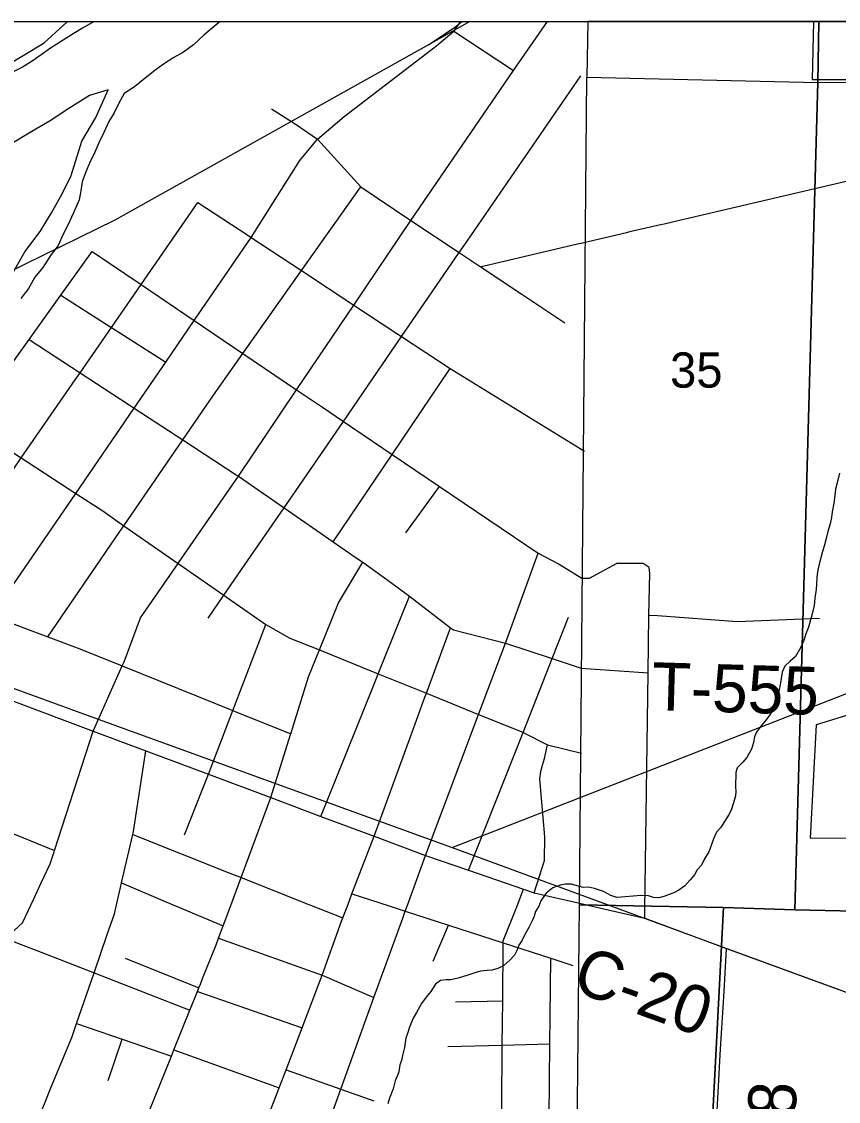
# Model space of a CAD drawing. Extents: x 0 to 34, y 0 to 22.
# Drawn here: x 24.174 to 25.144, y 19.618 to 20.9 of the extents above; entities that cross this region are included whole.
import ezdxf

# ---------------------------------------------------------------- set-up
doc = ezdxf.new("R2010")
doc.units = 0
for name, color, linetype in [('GM_X_City_Street', 7, 'Continuous'), ('GM_X_County_Road', 7, 'Continuous'), ('GM_X_County_Road_Text', 7, 'Continuous'), ('GM_X_Major_River', 7, 'Continuous'), ('GM_X_Minor_River', 7, 'Continuous'), ('GM_X_Rail_Line', 7, 'Continuous'), ('GM_X_Section', 7, 'Continuous'), ('GM_X_Section_Text', 7, 'Continuous'), ('GM_X_Township_Road', 7, 'Continuous'), ('GM_X_Township_Road_Text', 7, 'Continuous'), ('SH_Data', 7, 'Continuous')]:
    doc.layers.add(name, color=color, linetype=linetype)

msp = doc.modelspace()

# ---------------------------------------------------------------- linework, layer by layer
at = {"layer": 'GM_X_City_Street'}
for p, q in [((24.6877, 20.8886), (24.7583, 20.8418)), ((24.2211, 20.5754), (24.2792, 20.5381)), ((24.6307, 20.2929), (24.6705, 20.3482)), ((24.7491, 20.1622), (24.7876, 20.2689)), ((24.3677, 19.9347), (24.3964, 20.0064)), ((24.1512, 19.9411), (24.2136, 19.9158)), ((24.3064, 19.9349), (24.4215, 19.8892)), ((24.6631, 19.7846), (24.6812, 19.8273)), ((24.4083, 19.8119), (24.5315, 19.7681)), ((24.2976, 19.788), (24.3849, 19.753)), ((24.5315, 19.7681), (24.5928, 19.7413)), ((24.3832, 19.7487), (24.5076, 19.7055)), ((24.6896, 19.7363), (24.7457, 19.7375)), ((24.2773, 19.6427), (24.2938, 19.6918)), ((24.3553, 19.6792), (24.4804, 19.634))]:
    msp.add_line(p, q, dxfattribs=at)
for points in [[(23.8108, 20.6025), (23.8574, 20.6229), (23.8812, 20.6383), (23.9238, 20.6791), (23.9884, 20.7438), (24.0412, 20.7796), (24.1024, 20.8136), (24.1535, 20.846), (24.2011, 20.8749), (24.2281, 20.8995), (24.2286, 20.9)], [(24.5258, 20.7605), (24.5574, 20.7874), (24.6301, 20.8431), (24.6673, 20.8716), (24.6877, 20.8886), (24.6961, 20.9)], [(25.6303, 20.9), (25.1147, 20.9), (25.113, 20.8313), (25.279, 20.8313)], [(24.396, 20.1918), (24.4146, 20.2189), (24.4391, 20.2546), (24.486, 20.3228), (24.5565, 20.4254), (24.6256, 20.5261), (24.694, 20.6257), (24.7035, 20.6395), (24.8383, 20.8358)], [(24.4711, 20.7965), (24.4991, 20.7787), (24.5258, 20.7605)], [(24.2057, 20.1696), (24.2904, 20.2933), (24.296, 20.3014), (24.3658, 20.4034), (24.4023, 20.4566), (24.4372, 20.5061), (24.5068, 20.6044), (24.5772, 20.704)], [(24.1146, 20.2964), (24.1707, 20.3774), (24.174, 20.3822), (24.238, 20.4747), (24.2439, 20.4832), (24.2811, 20.5369), (24.3163, 20.5878), (24.3838, 20.6853)], [(24.3838, 20.6853), (24.4429, 20.6464), (24.4471, 20.6436), (24.5068, 20.6044), (24.5688, 20.5635), (24.6201, 20.5297)], [(24.0071, 20.2716), (24.0402, 20.3202), (24.0737, 20.3693), (24.1119, 20.4227), (24.1834, 20.5227), (24.2211, 20.5754), (24.2581, 20.6272)], [(24.2581, 20.6272), (24.3163, 20.5878), (24.3795, 20.5451), (24.4372, 20.5061), (24.501, 20.4629), (24.5317, 20.4422), (24.5565, 20.4254), (24.6145, 20.3861), (24.6705, 20.3482), (24.7876, 20.2689), (24.8126, 20.2557), (24.8395, 20.2394), (24.8488, 20.2394), (24.8808, 20.2567)], [(24.72, 20.6084), (24.7682, 20.5764), (24.8194, 20.5424)], [(24.2792, 20.5381), (24.2811, 20.5369), (24.3456, 20.4956)], [(24.6201, 20.5297), (24.6256, 20.5261), (24.6834, 20.488), (24.8428, 20.3902)], [(24.1834, 20.5227), (24.2439, 20.4832), (24.3021, 20.4451), (24.3082, 20.4411), (24.3658, 20.4034), (24.4293, 20.362), (24.4318, 20.3603)], [(24.5444, 20.2824), (24.6145, 20.3861), (24.6834, 20.488)], [(24.1135, 20.4217), (24.174, 20.3822), (24.2388, 20.3399), (24.2707, 20.319), (24.296, 20.3014), (24.3603, 20.2567), (24.4146, 20.2189), (24.4202, 20.215), (24.4645, 20.1842), (24.493, 20.1681), (24.528, 20.154), (24.5329, 20.152), (24.5978, 20.1257), (24.6551, 20.1026), (24.7171, 20.0775), (24.7676, 20.0571), (24.7698, 20.056), (24.799, 20.0413), (24.8394, 20.0315)], [(23.9157, 20.2781), (23.992, 20.2495), (24.1398, 20.1943), (24.2057, 20.1696), (24.2435, 20.1555), (24.2939, 20.1351), (24.4254, 20.082), (24.428, 20.0809), (24.494, 20.0543)], [(24.5298, 19.9564), (24.5921, 20.1114), (24.5978, 20.1257), (24.6349, 20.218)], [(24.7052, 19.8924), (24.7698, 20.056), (24.8017, 20.1367), (24.8045, 20.1438), (24.8239, 20.1931)], [(24.3964, 20.0064), (24.4254, 20.082), (24.4645, 20.1842)], [(24.5929, 19.9328), (24.6366, 20.052), (24.6534, 20.0979), (24.6551, 20.1026), (24.6836, 20.1804)], [(24.7491, 20.1622), (24.8045, 20.1438), (24.8103, 20.1419), (24.839, 20.1323)], [(25.3319, 20.1309), (25.1177, 20.0653), (25.1107, 19.9304), (25.1891, 19.9311)], [(24.7832, 19.8656), (24.7953, 19.9041), (24.7958, 19.9323), (24.7898, 20.0012), (24.7909, 20.0098), (24.7931, 20.0174), (24.7953, 20.025), (24.799, 20.0413)], [(23.9629, 19.1735), (24.0008, 19.2519), (24.0497, 19.3384), (24.0703, 19.3742), (24.112, 19.4297), (24.1428, 19.4837), (24.1587, 19.5115), (24.2023, 19.6172), (24.2092, 19.6341), (24.2339, 19.694), (24.2396, 19.7104), (24.2604, 19.7707), (24.2761, 19.816), (24.2847, 19.8408), (24.2883, 19.8565), (24.2919, 19.8721), (24.2931, 19.8774), (24.3064, 19.9349), (24.3072, 19.9386), (24.3221, 20.0342)], [(24.4571, 19.5738), (24.4804, 19.634), (24.4886, 19.6556), (24.5076, 19.7055), (24.5315, 19.7681), (24.5544, 19.8322), (24.5557, 19.8359), (24.5616, 19.8511), (24.5667, 19.8645), (24.5929, 19.9328)], [(24.4215, 19.8892), (24.4351, 19.8838), (24.5153, 19.852), (24.5557, 19.8359)], [(24.2931, 19.8774), (24.345, 19.8554), (24.4137, 19.8263)], [(24.5667, 19.8645), (24.611, 19.8501), (24.6229, 19.8462), (24.63, 19.8439), (24.6812, 19.8273), (24.7462, 19.8063), (24.8027, 19.7879), (24.8291, 19.7794)], [(24.7446, 19.4144), (24.7446, 19.4593), (24.7446, 19.5266), (24.7446, 19.557), (24.7445, 19.5967), (24.7447, 19.6129), (24.7452, 19.6848), (24.7455, 19.7113), (24.7457, 19.7375), (24.7462, 19.8063), (24.7462, 19.8086), (24.7615, 19.8472), (24.7705, 19.8699)], [(24.7446, 19.4593), (24.7713, 19.4585), (24.7875, 19.4618), (24.7908, 19.4629), (24.7967, 19.4657), (24.7986, 19.4681), (24.7994, 19.4715), (24.8, 19.5289), (24.8003, 19.5559), (24.8016, 19.6863), (24.802, 19.7187), (24.8027, 19.7879)], [(24.2396, 19.7104), (24.2938, 19.6918), (24.3523, 19.6717)], [(24.6807, 19.6831), (24.7452, 19.6848), (24.8016, 19.6863)], [(24.4886, 19.6556), (24.5535, 19.6327), (24.5928, 19.6189)]]:
    msp.add_lwpolyline(points, dxfattribs=at)
at = {"layer": 'GM_X_County_Road'}
for p, q in [((24.8389, 19.8528), (24.8672, 19.8463)), ((24.1554, 19.8116), (24.203, 19.7931))]:
    msp.add_line(p, q, dxfattribs=at)
for points in [[(24.6366, 20.664), (24.7583, 20.8418), (24.7987, 20.9)], [(24.138, 20.19), (24.1398, 20.1943), (24.1411, 20.1974), (24.1645, 20.2315), (24.2388, 20.3399), (24.3082, 20.4411), (24.3456, 20.4956), (24.3795, 20.5451), (24.4471, 20.6436), (24.5049, 20.7351), (24.5258, 20.7605)], [(24.5258, 20.7605), (24.5772, 20.704), (24.6366, 20.664)], [(24.9673, 20.6671), (25.2835, 20.741), (25.2924, 20.7431)], [(24.9372, 20.6601), (24.9624, 20.666), (24.9673, 20.6671)], [(24.3609, 20.2575), (24.4318, 20.3603), (24.501, 20.4629), (24.5688, 20.5635), (24.6366, 20.664)], [(24.6366, 20.664), (24.694, 20.6257), (24.72, 20.6084), (24.721, 20.6091)], [(24.8982, 20.651), (24.9332, 20.6591), (24.9372, 20.6601)], [(24.8389, 20.6371), (24.8943, 20.65), (24.8982, 20.651)], [(24.721, 20.6091), (24.7221, 20.6098), (24.8359, 20.6364), (24.8389, 20.6371)], [(24.4318, 20.3603), (24.486, 20.3228), (24.5444, 20.2824), (24.5718, 20.2635)], [(24.2962, 20.1401), (24.2974, 20.1429), (24.3156, 20.192), (24.3603, 20.2567), (24.3609, 20.2575)], [(24.4704, 19.9787), (24.4937, 20.0535), (24.494, 20.0543), (24.515, 20.122), (24.528, 20.154), (24.5507, 20.2098), (24.5796, 20.2581)], [(24.5718, 20.2635), (24.5796, 20.2581), (24.6123, 20.2344), (24.6349, 20.218), (24.6836, 20.1804), (24.6872, 20.1777), (24.7491, 20.1622)], [(24.6539, 19.91), (24.7171, 20.0775), (24.7491, 20.1622)], [(24.2131, 19.9143), (24.2136, 19.9158), (24.2595, 20.0576), (24.2939, 20.1351), (24.2962, 20.1401)], [(24.1067, 20.1148), (24.2595, 20.0576), (24.3221, 20.0342), (24.3964, 20.0064), (24.4704, 19.9787), (24.5298, 19.9564), (24.5929, 19.9328), (24.6539, 19.91), (24.7052, 19.8924), (24.7705, 19.8699), (24.7832, 19.8656), (24.8389, 19.8528)], [(24.4215, 19.8474), (24.4239, 19.8538), (24.4351, 19.8838), (24.4704, 19.9787)], [(24.1978, 19.8774), (24.2084, 19.9), (24.2131, 19.9143)], [(24.627, 19.8356), (24.63, 19.8439), (24.6321, 19.8497), (24.6539, 19.91)], [(24.1554, 19.8116), (24.1754, 19.8299), (24.1889, 19.8585), (24.1978, 19.8774)], [(24.3893, 19.7639), (24.4054, 19.8041), (24.4083, 19.8119), (24.4137, 19.8263), (24.4215, 19.8474)], [(24.8672, 19.8463), (24.9143, 19.8355), (25.0113, 19.7995)], [(24.5165, 19.5304), (24.5535, 19.6327), (24.5928, 19.7413), (24.627, 19.8356)], [(25.0013, 19.6291), (25.0041, 19.6803), (25.0087, 19.7486), (25.0113, 19.7995)], [(25.0113, 19.7995), (25.3711, 19.6682), (25.4041, 19.6559)], [(24.203, 19.7931), (24.2604, 19.7707), (24.3743, 19.7264)], [(24.3256, 19.6051), (24.3523, 19.6717), (24.3553, 19.6792), (24.3743, 19.7264), (24.3832, 19.7487), (24.3849, 19.753), (24.3867, 19.7574), (24.3893, 19.7639)], [(24.9991, 19.5889), (24.9994, 19.593), (25.0013, 19.6291)]]:
    msp.add_lwpolyline(points, dxfattribs=at)
at = {"layer": 'GM_X_Major_River'}
for points in [[(24.2606, 20.9), (24.2578, 20.8984), (24.2467, 20.8921), (24.2356, 20.8854), (24.2238, 20.8779), (24.2089, 20.8686), (24.1978, 20.8607), (24.1871, 20.8529), (24.1756, 20.8458), (24.163, 20.8394)], [(24.4101, 20.9), (24.3911, 20.8841), (24.3785, 20.8724), (24.3666, 20.8638), (24.3552, 20.8575), (24.343, 20.8493), (24.3326, 20.8418), (24.3211, 20.8328), (24.3085, 20.8227), (24.2963, 20.8145), (24.2897, 20.8032), (24.2843, 20.7918), (24.2781, 20.7813), (24.2719, 20.7684), (24.266, 20.756), (24.2613, 20.745), (24.2551, 20.7318), (24.2508, 20.7216), (24.2465, 20.7099), (24.2449, 20.6989), (24.2429, 20.6883), (24.2362, 20.6728), (24.2293, 20.6584), (24.2238, 20.6478), (24.218, 20.6342), (24.2095, 20.6233), (24.1995, 20.6079), (24.1902, 20.5966), (24.1825, 20.583), (24.1736, 20.5713)], [(24.2774, 20.8189), (24.2549, 20.8123), (24.2305, 20.797), (24.2083, 20.782), (24.1865, 20.7697), (24.1598, 20.7533)], [(24.2333, 20.7172), (24.246, 20.7581), (24.2626, 20.7863), (24.2774, 20.8189)], [(24.1653, 20.6037), (24.1781, 20.6267), (24.1965, 20.6508), (24.2101, 20.673), (24.2225, 20.6957), (24.2333, 20.7172)]]:
    msp.add_lwpolyline(points, dxfattribs=at)
at = {"layer": 'GM_X_Minor_River'}
for points in [[(25.1454, 20.3639), (25.1434, 20.3556), (25.141, 20.345), (25.1398, 20.3344), (25.1389, 20.3283), (25.1369, 20.3181), (25.1361, 20.3113), (25.1345, 20.3037), (25.1317, 20.2946), (25.1297, 20.2863), (25.1274, 20.2772), (25.1254, 20.2708), (25.121, 20.2541), (25.1194, 20.2469), (25.1186, 20.2401), (25.1181, 20.2321), (25.1177, 20.226), (25.1164, 20.2154), (25.1156, 20.2067), (25.1128, 20.1953), (25.1112, 20.1897), (25.1088, 20.181), (25.1057, 20.173), (25.1033, 20.1651), (25.0991, 20.1564), (25.0933, 20.1462), (25.0871, 20.1406), (25.0806, 20.1349), (25.0775, 20.1278), (25.0759, 20.1179), (25.075, 20.1126), (25.0738, 20.1069), (25.0722, 20.0975), (25.0706, 20.0906), (25.0664, 20.0835), (25.0636, 20.0782), (25.0586, 20.071), (25.0521, 20.0635), (25.0471, 20.0563), (25.0447, 20.0507), (25.0435, 20.0442), (25.0412, 20.0363), (25.0354, 20.0265), (25.0308, 20.0208), (25.0242, 20.0141), (25.0223, 20.0084), (25.0221, 19.9917), (25.0224, 19.986), (25.022, 19.9807), (25.0196, 19.9724), (25.0172, 19.9648), (25.0145, 19.9591), (25.0091, 19.9505), (25.0041, 19.9429)], [(25.0041, 19.9429), (24.9995, 19.9377), (24.996, 19.9297), (24.9932, 19.9218), (24.9905, 19.9142), (24.9854, 19.9059), (24.9816, 19.8987), (24.9766, 19.8931), (24.9735, 19.8871), (24.9681, 19.881), (24.9619, 19.8739), (24.9547, 19.869), (24.9489, 19.8657), (24.9432, 19.8635), (24.9368, 19.8613), (24.9311, 19.8598), (24.9246, 19.8603), (24.9189, 19.8622), (24.9095, 19.8623), (24.9007, 19.8616), (24.8863, 19.8607), (24.881, 19.8603), (24.8742, 19.8623), (24.8655, 19.8673), (24.8546, 19.8709), (24.8477, 19.8725), (24.8413, 19.8718), (24.8341, 19.8741), (24.8273, 19.8761), (24.8197, 19.8758), (24.814, 19.8747), (24.8052, 19.8714), (24.7972, 19.8654), (24.791, 19.856), (24.7887, 19.8499), (24.7848, 19.8435), (24.7829, 19.8379), (24.7805, 19.8326), (24.7766, 19.8246), (24.772, 19.816), (24.7689, 19.8095), (24.765, 19.8035), (24.7627, 19.7978), (24.7596, 19.7918), (24.7542, 19.7858), (24.7469, 19.7794), (24.7397, 19.7757), (24.7332, 19.7738), (24.7271, 19.7735), (24.7192, 19.7725), (24.7115, 19.7703), (24.7043, 19.7681), (24.6929, 19.7644), (24.6841, 19.7622), (24.6784, 19.7623), (24.672, 19.7616), (24.6659, 19.7571), (24.6605, 19.7484), (24.6547, 19.7417), (24.6493, 19.7341), (24.6435, 19.7236), (24.6392, 19.7168), (24.6349, 19.7062), (24.6326, 19.6986), (24.6306, 19.6933), (24.6298, 19.688), (24.629, 19.682), (24.6266, 19.6725), (24.6254, 19.6668), (24.6234, 19.6615), (24.6222, 19.6532), (24.6202, 19.6479), (24.6179, 19.6426), (24.6155, 19.6331), (24.6112, 19.6218), (24.6092, 19.615)]]:
    msp.add_lwpolyline(points, dxfattribs=at)
at = {"layer": 'GM_X_Rail_Line'}
msp.add_line((24.7068, 20.9), (24.6575, 20.8724), dxfattribs=at)
for points in [[(24.6575, 20.8724), (24.6901, 20.8943), (24.6973, 20.9)], [(24.6857, 19.9193), (25.3089, 20.1629), (25.713, 20.3036), (25.9724, 20.3916), (26.54, 20.6067), (26.7751, 20.7), (27.3361, 20.9)], [(24.6575, 20.8724), (24.2851, 20.6641), (24.1348, 20.5905)], [(23.8272, 20.2163), (23.9111, 20.201), (24.274, 20.0685), (24.6857, 19.9193)], [(24.6857, 19.9193), (25.0148, 19.7985), (25.4772, 19.6296), (26.0332, 19.4244), (26.618, 19.2083), (27.1754, 19.0083), (27.8265, 18.7785), (28.397, 18.5695), (29.2915, 18.2251), (29.5147, 18.1387)]]:
    msp.add_lwpolyline(points, dxfattribs=at)
at = {"layer": 'GM_X_Section'}
for points in [[(25.1211, 20.9), (24.8466, 20.9), (24.8455, 20.8339), (25.1198, 20.8277)], [(26.1071, 20.9), (25.1211, 20.9), (25.1198, 20.8277), (26.1064, 20.8349)], [(25.1198, 20.8277), (25.0925, 19.8455), (25.0077, 19.8483), (24.8367, 19.8516), (24.8455, 20.8339)], [(26.1064, 20.8349), (26.1071, 20.822), (26.0975, 19.8234), (25.0925, 19.8455), (25.1198, 20.8277)], [(25.0077, 19.8483), (24.9624, 18.9716), (23.916, 18.9723), (23.9162, 19.1808), (24.83, 19.1865), (24.8367, 19.8516)], [(25.0077, 19.8483), (25.0925, 19.8455), (26.0975, 19.8234), (26.0616, 18.9227), (26.0607, 18.8928), (24.9624, 18.9716)]]:
    msp.add_lwpolyline(points, close=True, dxfattribs=at)
at = {"layer": 'GM_X_Township_Road'}
for p, q in [((24.919, 20.1955), (24.9296, 20.1948)), ((24.839, 20.1323), (24.9182, 20.1267)), ((24.9143, 19.8355), (24.9145, 19.8455))]:
    msp.add_line(p, q, dxfattribs=at)
for points in [[(24.9145, 19.8455), (24.9182, 20.1267), (24.919, 20.1955), (24.9202, 20.2449), (24.9197, 20.252), (24.9126, 20.2565), (24.8942, 20.2568), (24.8808, 20.2567)], [(24.9296, 20.1948), (25.0241, 20.1879), (25.1217, 20.1918)]]:
    msp.add_lwpolyline(points, dxfattribs=at)
at = {"layer": 'SH_Data'}
msp.add_lwpolyline([(23.5167, 20.9), (30.3167, 20.9), (30.3167, 14.1), (23.5167, 14.1)], close=True, dxfattribs=at)

# ---------------------------------------------------------------- texts
at = {"layer": 'GM_X_County_Road_Text'}
for s, rotation, p in [('C-20', 340.1025, (24.826, 19.7504)), ('C-178', 87.2485, (25.0852, 19.4335))]:
    msp.add_text(s, height=0.05682, rotation=rotation, dxfattribs=at).set_placement(p)
at = {"layer": 'GM_X_Section_Text'}
msp.add_text('35', height=0.04186, rotation=0, dxfattribs=at).set_placement((24.9444, 20.4654))
at = {"layer": 'GM_X_Township_Road_Text'}
msp.add_text('T-555', height=0.05682, rotation=358.3152, dxfattribs=at).set_placement((24.922, 20.0827))

doc.saveas('drawing.dxf')
